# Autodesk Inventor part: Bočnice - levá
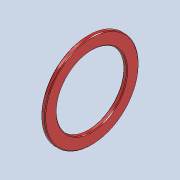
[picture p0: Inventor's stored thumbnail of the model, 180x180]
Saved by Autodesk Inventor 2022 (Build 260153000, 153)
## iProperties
Created: 2025-05
Part Number: Bočnice - levá
Material: Všeobecné
Document SubType Name: Modeling
Designer: jbart
Density: 1 g/cm^3
Appearance: Oranžovo-červená
Mass: 5244.89 g
Surface Area: 4518.21 cm^2
Volume: 5244.89 cm^3
Author: jbart
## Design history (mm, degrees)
sketch "Náčrt1"
  geometry: L1 (0, 0)-(30, 0); L2 (0, 360)-(30, 360); L3 (30, 360)-(30, 270); L4 (30, 270)-(0, 270); L5 (0, 270)-(0, 360); 2 further points
  constraints: 10 end point, 2 horizontal, 2 midpoint, 2 parallel, 2 vertical alignment, 1 perpendicular
  dimensions: "d0" = 30 distance of L1.start L1.end; "d1" = 540 diameter of L4 L1; "d2" = 720 diameter of L2 L1
revolve "Rotace1" sketch "Náčrt1" stored, may be unused: angle "d3" = 90 deg
chamfer "Zkosení1" distance "d4" = 5; stored, may be unused: second distance "d5" = 2, angle "d6" = 45 deg
node "Těleso1"
